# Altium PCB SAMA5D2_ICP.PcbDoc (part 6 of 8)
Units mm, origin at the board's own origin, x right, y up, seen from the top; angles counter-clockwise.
Board outline 150 x 100 mm, 6 copper layers (L1 - TOP, L2 - GND, L3 - SIG, L4 - SIG, L5 - VCC, L6 - BOT), stack 1.512 mm thick; 708 components, 597 nets, 2710 pads, 1437 vias.
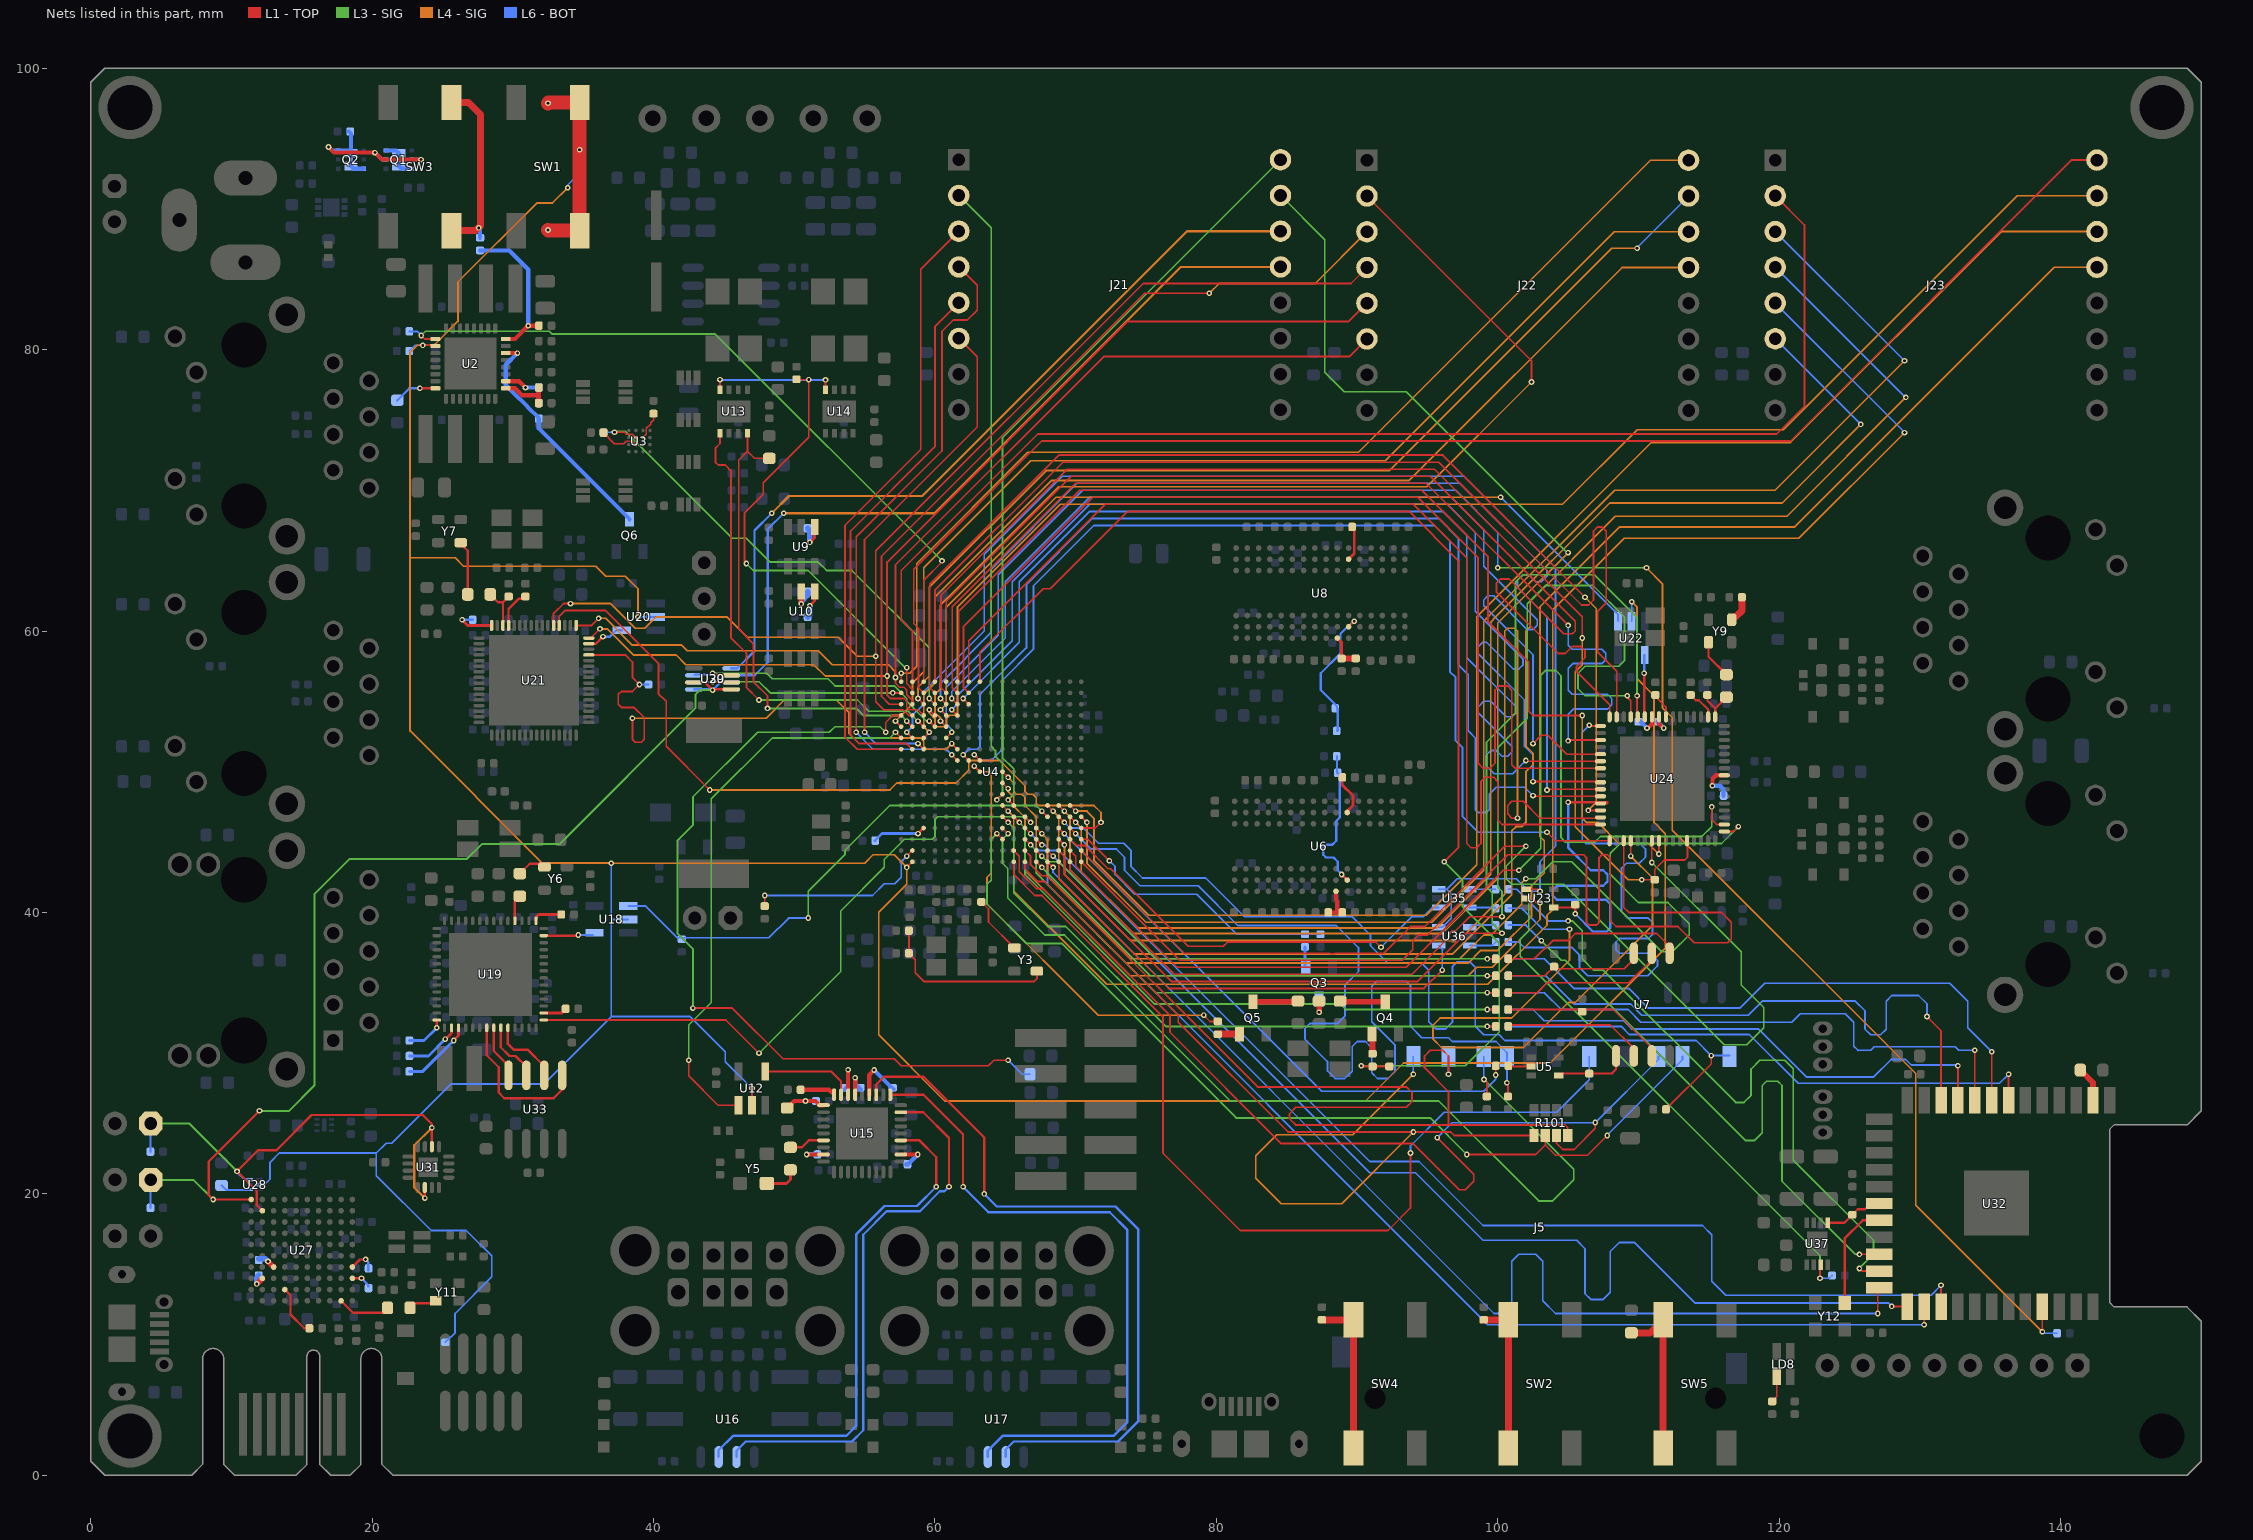
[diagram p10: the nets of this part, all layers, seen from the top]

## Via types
v1: diameter 0.4, hole 0.2, L1 - TOP to L6 - BOT, tented both sides, 1312 vias
v2: diameter 0.55, hole 0.3, L1 - TOP to L6 - BOT, 84 vias
v3: diameter 0.4, hole 0.2, L1 - TOP to L6 - BOT, tented top, 25 vias
v4: diameter 0.55, hole 0.3, L1 - TOP to L6 - BOT, tented bottom, 16 vias

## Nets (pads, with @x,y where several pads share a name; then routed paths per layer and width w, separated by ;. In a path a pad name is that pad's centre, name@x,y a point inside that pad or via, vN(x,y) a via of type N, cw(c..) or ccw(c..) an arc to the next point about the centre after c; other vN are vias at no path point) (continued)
NetLD8_4: LD8.4 R258.1 | length 1.9
  L1 - TOP w0.14: R258.1@119.5,5.25 119.825,5.575 LD8.4@119.825,7
NetQ1_2: Q1.2 Q1.5 Q2.3 Q2.6 Q2.7 Q2.8 R13.1 | length 14.1
  L1 - TOP w0.3: v1(16.9,94.4) 17.3,94 v1(20.2,94) 20.7,93.5 v1(23.475,93.5)
  L6 - BOT w0.3: v1(16.9,94.4) 17.15,94.15 Q2.3@17.587,94.15 Q2.8@18.305,94.15 ; R13.1@18.35,95.5 18.5,95.35 Q2.8@18.5,94.15 ; Q2.8@18.525,94.15 Q2.8@18.5,94.15 ; Q2.6@19.413,92.85 18.695,92.85 Q2.7@18.5,93.045 Q2.8@18.5,93.955 ; v1(20.2,94) 20.7,93.5 Q1.2@20.987,93.5 ; Q1.5@22.813,93.5 v1(23.475,93.5) ; Q2.8@18.305,94.15 Q2.8@18.5,94.15 ; Q2.8@18.305,94.15 Q2.8@18.5,93.955 ; Q2.8@18.5,93.955 Q2.8@18.5,94.15
NetQ1_3: Q1.3 Q1.6 Q1.7 Q1.8 | length 2.9
  L6 - BOT w0.3: Q1.3@20.987,94.15 21.705,94.15 Q1.8@21.9,93.955 Q1.7@21.9,93.045 22.095,92.85 Q1.6@22.813,92.85
NetQ3_1: Q3.1 R239.2 | length 1.4
  L6 - BOT w0.2: R239.2@86.3,37.55 86.3,36.2 Q3.1@86.35,36.15
NetQ3_3: Q3.3 R244.1 | length 1.7
  L1 - TOP w0.4: v1(87.3,32.9) R244.1@87.3,33.7
  L6 - BOT w0.2: v1(87.3,32.9) Q3.3@87.3,33.85
NetQ4_1: Q4.1 R240.2 | length 1.4
  L1 - TOP w0.4: Q4.1@91.05,31.35 91.1,31.3 R240.2@91.1,29.95
NetQ4_3: Q4.3 R245.1 | length 3.2
  L1 - TOP w0.4: R245.1@88.8,33.7 88.85,33.65 Q4.3@92,33.65
NetQ5_1: Q5.1 R241.2 | length 1.5
  L1 - TOP w0.5: R241.2@80.1,31.35 Q5.1@81.65,31.35
NetQ5_3: Q5.3 R246.1 | length 3.2
  L1 - TOP w0.4: Q5.3@82.6,33.65 85.75,33.65 R246.1@85.8,33.7
NetQ6_3: Q6.3 R72.1 U2.22 | length 16.6
  L1 - TOP w0.3: U2.22@29.5,79.75 v1(30.325,79.75)
  L6 - BOT w0.3: v1(30.325,79.75) 29.5,78.925 29.5,77.475 30.525,76.45 30.552,76.45 31.05,75.952 31.05,75.925 31.85,75.125 R72.1@31.85,75.1 31.85,74.4 Q6.3@38.3,67.95
NetR4_2: R4.2 R178.2 U6.L2 | length 10.5
  L1 - TOP w0.165: v1(88.9,42.7) U6.L2@89.3,42.3
  L6 - BOT w0.165: R178.2@88.575,51.1 88.575,49.95 88.775,49.75 88.775,46.75 88.525,46.5 88.525,45.1 88.225,44.8 87.8,44.8 87.6,44.6 87.6,44.1 87.8,43.9 88.325,43.9 88.625,43.6 88.625,43 v1@88.825,42.8
NetR6_2: R6.2 U2.8 | length 3.1
  L1 - TOP w0.165: v1(23.4,77.25) U2.8@24.5,77.25
  L6 - BOT w0.165: R6.2@21.8,76.4 22.65,77.25 v1(23.4,77.25)
NetR7_1: R7.1 R8.2 U2.17 | length 3.7
  L1 - TOP w0.3: U2.17@29.5,77.25 30.15,77.25 30.65,76.75 31.85,76.75 ; R7.1@31.85,76.2 31.85,76.75 ; R8.2@31.85,77.3 31.85,76.75
NetR9_1: R9.1 R10.2 U2.18 | length 3.6
  L1 - TOP w0.3: U2.18@29.5,77.75 30.45,77.75 v1(30.9,77.3)
  L6 - BOT w0.3: v1(30.9,77.3) R10.2@31.85,77.3 R9.1@31.85,76.2
NetR22_2: R22.2 U3.C2 | length 2.1
  L1 - TOP w0.1: U3.C2@39.25,73.75 39.5,74 39.5,74.4 39.8,74.7 39.8,74.8 40,75 R22.2@40,75.45 R22.2@40,75.55
NetR23_1: R23.1 U3.B3 | length 2.8
  L1 - TOP w0.1: R23.1@36.45,74.1 37.225,73.325 37.875,73.325 38.05,73.5 38.5,73.5 U3.B3@38.75,73.25
NetR27_1: R27.1 U36.1 | length 1.9
  L6 - BOT w0.125: U36.1@98,38.95 98.15,39.1 R27.1@99.85,39.1
NetR28_1: R28.1 U36.3 | length 2
  L6 - BOT w0.125: U36.3@98,37.65 99.6,37.65 R28.1@99.85,37.9
NetR29_1: R29.1 U35.1 | length 1.9
  L6 - BOT w0.125: U35.1@97.996,41.65 R29.1@99.85,41.65
NetR30_1: R30.1 U35.3 | length 1.9
  L6 - BOT w0.125: U35.3@97.996,40.35 99.8,40.35 R30.1@99.85,40.3
NetR66_1: R66.1 U4.P3 | length 3.8
  L1 - TOP w0.2: v1(58.8,45.6) U4.P3@59.2,46
  L6 - BOT w0.2: R66.1@55.75,45.1 56.25,45.6 v1(58.8,45.6)
NetR69_1: R69.1 Y3.3 | length 4.2
  L1 - TOP w0.125: R69.1@63.3,40.75 63.805,40.245 63.805,39.319 Y3.3@65.646,37.477
NetR75_2: R75.2 U4.T2 | length 13.2
  L1 - TOP w0.125: R75.2@47.9,40.45 v1(47.9,41.2) ; v1(58,44) U4.T2@58.4,44.4
  L6 - BOT w0.125: v1(47.9,41.2) 55.566,41.2 56.4,42.034 57.134,42.034 57.6,42.5 57.6,43.6 v1(58,44)
NetR83_1: R83.1 U5.4 U7.1 | length 5.2
  L1 - TOP w0.165: U5.4@104.335,28.4 104.485,28.55 108.1,28.55 ; 108.125,28.55 108.1,28.55 ; U7.1@108.4,29.775 108.4,28.85 108.1,28.55
NetR85_2: R85.2 U6.L8 | length 2.9
  L1 - TOP w0.2: R85.2@88.95,49.6 88.95,49.05 89.7,48.3 89.7,47.6 U6.L8@89.3,47.2
NetR86_2: R86.2 R87.2 U6.K1 | length 2.6
  L1 - TOP w0.305: R87.2@87.95,40 88.45,40 ; U6.K1@88.5,41.5 88.5,40.9 88.6,40.8 88.6,40.15 88.45,40 ; R86.2@88.95,40 88.45,40
NetR89_2: R89.2 R184.2 U8.L2 | length 9.8
  L1 - TOP w0.165: U8.L2@89.375,60.3 v1@89.775,60.7
  L6 - BOT w0.165: R89.2@88.575,52.9 88.625,52.95 88.625,54.45 88.575,54.5 88.575,54.66 87.425,55.81 87.425,57 88.825,58.4 88.825,59.8 v1@89.725,60.7
  other v1: 89.8,60.7
NetR91_2: R91.2 U9.4 | length 2.2
  L1 - TOP w0.2: v1(51.1,66.3) 51.125,66.3 51.45,66.625 U9.4@51.45,67.3
  L6 - BOT w0.4: R91.2@50.95,67.3 51.1,67.15 v1(51.1,66.3)
NetR92_2: R92.2 U8.L8 | length 2.5
  L1 - TOP w0.2: U8.L8@89.4,65.1 89.8,65.5 R92.2@89.8,67.4
NetR94_2: R94.2 R95.2 U8.K1 | length 2.6
  L1 - TOP w0.2: U8.K1@88.6,59.5 88.9,59.2 R95.2@88.9,58.05
  L1 - TOP w0.4: R95.2@88.9,58.05 R94.2@89.9,58.05
NetR97_1: R97.1 U10.4 | length 2
  L1 - TOP w0.2: v1(51.1,61.8) 51.125,61.8 51.45,62.125 U10.4@51.45,62.8
  L6 - BOT w0.4: R97.1@50.95,61 51.1,61.15 v1(51.1,61.8)
NetR98_1: R98.1 U10.5 | length 1.9
  L1 - TOP w0.4: v1(50.5,61.925) U10.5@50.5,62.8
  L6 - BOT w0.4: v1(50.5,61.925) 50.5,62.1 50.95,62.55 R98.1@50.95,62.8
NetR108_1: R108.1 Y5.3 | length 2.5
  L1 - TOP w0.2: Y5.3@48.055,20.742 49.444,20.742 49.733,21.031 R108.1@49.733,21.704
NetR108_2: R108.2 U15.33 | length 2.6
  L1 - TOP w0.165: R108.2@49.733,23.304 50.533,23.304 51.029,23.8 U15.33@52.08,23.8
NetR111_2: R111.2 U15.11 | length 2.4
  L1 - TOP w0.3: U15.11@57.58,22.8 v1(58.78,22.8)
  L6 - BOT w0.3: R111.2@57.95,22.1 R111.2@58.05,22.1 58.08,22.1 v1(58.78,22.8) v1@58.755,22.825
NetR112_1: R112.1 U15.35 | length 2.1
  L1 - TOP w0.3: v1(50.88,22.8) U15.35@52.08,22.8
  L6 - BOT w0.3: v1(50.88,22.8) 50.905,22.825 R112.1@51.73,22.825
NetR113_1: R113.1 U15.27 | length 2.5
  L1 - TOP w0.3: R113.1@50.45,27.4 52.48,27.4 U15.27@52.83,27.05
NetR120_1: R120.1 U15.22 | length 3.9
  L1 - TOP w0.3: U15.22@55.33,27.05 55.33,28.45 v1(55.68,28.8)
  L6 - BOT w0.3: v1(55.68,28.8) 57.03,27.45 R120.1@57.03,27.4
NetR121_1: R121.1 U15.24 | length 2.2
  L1 - TOP w0.3: U15.24@54.33,27.05 v1(54.33,28.25)
  L6 - BOT w0.3: v1(54.33,28.25) 54.33,27.8 R121.1@54.73,27.4
NetR122_1: R122.1 U15.25 | length 3.3
  L1 - TOP w0.3: U15.25@53.83,27.05 v1(53.83,28.825)
  L6 - BOT w0.3: R122.1@53.58,27.4 53.83,27.65 v1(53.83,28.825)
NetR123_1: R123.1 R124.1 U15.28 | length 3.5
  L1 - TOP w0.3: R124.1@49.5,26.1 50,26.6 v1(50.8,26.6) 51.5,26.6 51.8,26.3 U15.28@52.08,26.3
  L6 - BOT w0.3: v1(50.8,26.6) R123.1@51.378,26.6
NetR132_1: R132.1 U19.30 | length 1.7
  L1 - TOP w0.229: U19.30@32.2,32.85 33.445,32.85 R132.1@33.75,33.155
NetR133_1: R133.1 U19.43 | length 2.1
  L1 - TOP w0.229: U19.43@31.65,39.4 31.65,39.65 31.855,39.855 R133.1@33.45,39.855
NetR134_1: R134.1 U19.14 | length 2.9
  L1 - TOP w0.2: v1(24.6,31.8) U19.14@24.6,32.35
  L6 - BOT w0.2: R134.1@22.653,30.9 23.7,30.9 v1(24.6,31.8)
NetR135_1: R135.1 Y6.3 | length 1.9
  L1 - TOP w0.165: R135.1@30.5,42.755 31.2,43.455 Y6.3@32.1,43.455
NetR135_2: R135.2 U19.46 | length 1.9
  L1 - TOP w0.165: U19.46@30.15,39.4 30.15,40.805 R135.2@30.5,41.155
NetR146_2: R146.2 U21.61 | length 2.7
  L1 - TOP w0.165: U21.61@29.7,60.4 29.7,61.556 30.444,62.3 30.75,62.3 R146.2@30.9,62.45
NetR147_2: R147.2 R148.2 U21.62 | length 3.3
  L1 - TOP w0.165: R148.2@28.4,62.6 28.95,62.05 29.3,62.05 ; U21.62@29.3,60.4 29.3,62.05 ; R147.2@29.7,62.45 29.3,62.05
NetR148_1: R148.1 Y7.3 | length 3.6
  L1 - TOP w0.165: Y7.3@26.45,66.05 26.8,65.7 R148.1@26.8,62.6
NetR149_2: R149.2 U21.64 | length 3
  L1 - TOP w0.2: v1(26.4,60.8) 26.8,60.4 U21.64@28.5,60.4
  L6 - BOT w0.2: v1(26.4,60.8) R149.2@27.15,60.8
NetR150_1: R150.1 U19.16 | length 4.1
  L1 - TOP w0.2: v1(25.2,31) 25.228,31 25.5,31.272 ; 25.504,31.272 25.5,31.272 ; U19.16@25.65,31.8 25.65,31.422 25.5,31.272
  L6 - BOT w0.2: R150.1@22.653,29.8 24,29.8 v1(25.2,31)
NetR151_1: R151.1 U19.17 | length 5.1
  L1 - TOP w0.2: v1(25.8,30.9) 26.15,31.25 U19.17@26.15,31.8
  L6 - BOT w0.229: R151.1@22.65,28.7 23.6,28.7 v1(25.8,30.9)
NetR165_1: R165.1 Y9.1 | length 1.6
  L1 - TOP w0.5: Y9.1@116.85,60.95 117.371,61.471 ; 117.35,61.492 R165.1@117.35,62.4
NetR166_2: R166.2 R185.2 Y3.1 | length 12.7
  L1 - TOP w0.125: R185.2@58.15,38.7 R166.2@58.15,37.1 58.6,36.65 58.6,35.7 59.2,35.1 67.053,35.1 67.246,35.293 Y3.1@67.246,35.827
NetR168_1: R168.1 Y9.3 | length 2.8
  L1 - TOP w0.165: Y9.3@114.975,59.2 114.975,58.175 R168.1@116.25,56.9
NetR168_2: R168.2 R169.2 U24.1 | length 2.9
  L1 - TOP w0.165: R169.2@114.9,55.45 114.9,55.05 115.45,54.5 ; U24.1@115.45,53.9 115.45,54.5 ; R168.2@116.25,55.3 115.45,54.5
NetR170_2: R170.2 U24.2 | length 2.2
  L1 - TOP w0.165: R170.2@113.7,55.45 114.075,55.075 114.287,55.075 114.95,54.412 U24.2@114.95,53.9
NetR174_1: R174.1 U24.57 | length 2.8
  L1 - TOP w0.3: v1(115.25,49) 115.25,49.5 115.5,49.75 U24.57@116.1,49.75
  L6 - BOT w0.3: v1(115.25,49) 115.8,49 116.05,48.75 R174.1@116.05,48.3
NetR175_2: R175.2 U24.8 | length 1.8
  L1 - TOP w0.125: R175.2@111.2,55.35 111.95,54.6 U24.8@111.95,53.9
NetR180_1: R180.1 U24.9 | length 1.6
  L1 - TOP w0.3: U24.9@111.45,53.9 111.45,53.388 111.738,53.1 v1(111.8,53.1)
  L6 - BOT w0.3: R180.1@111.35,53.55 v1(111.8,53.1)
NetR181_1: R181.1 U24.10 | length 1.6
  L1 - TOP w0.3: v1(110.6,53.1) 110.662,53.1 110.95,53.388 U24.10@110.95,53.9
  L6 - BOT w0.3: R181.1@110.15,53.55 v1(110.6,53.1)
NetR200_2: R200.2 U27.B7 | length 3.7
  L1 - TOP w0.165: U27.B7@13.8,13.2 14.2,12.8 14.2,11.425 15.175,10.45 R200.2@15.55,10.45
NetR202_1: R202.1 Y11.3 | length 2
  L1 - TOP w0.165: R202.1@22.7,11.9 23.025,12.225 Y11.3@24.525,12.225
NetR202_2: R202.2 U27.A2 | length 3.7
  L1 - TOP w0.165: U27.A2@17.8,12.4 18.65,11.55 R202.2@21.1,11.55
NetR203_2: R203.2 U27.D1 | length 2
  L1 - TOP w0.165: U27.D1@18.6,14.8 19.14,15.34 v1(19.54,15.34)
  L6 - BOT w0.165: v1(19.54,15.34) 19.725,15.155 R203.2@19.725,14.575
NetR204_2: R204.2 U27.C1 | length 1.4
  L1 - TOP w0.165: U27.C1@18.6,14 v1(19.25,14)
  L6 - BOT w0.165: v1(19.25,14) 19.725,13.525 R204.2@19.725,13.425
NetR205_2: R205.2 U27.C9 | length 1.2
  L1 - TOP w0.4: v1(11.8,13.6) U27.C9@12.2,14
  L6 - BOT w0.4: v1(11.8,13.6) 11.8,14.05 R205.2@11.95,14.2
NetR207_2: R207.2 U27.D8 | length 1.3
  L1 - TOP w0.4: v1(12.6,15.2) U27.D8@13,14.8
  L6 - BOT w0.4: R207.2@11.95,15.4 12.4,15.4 v1(12.6,15.2)
NetR216_2: R216.2 U28.4 | length 2.1
  L6 - BOT w0.15: R216.2@9.3,20.6 9.625,20.275 11.275,20.275 U28.4@11.3,20.3
NetR247_1: R247.1 U32.19 U37.5 | length 4.4
  L1 - TOP w0.165: U37.5@123.45,17.95 124.635,17.95 R247.1@125.2,18.515 125.585,18.9 126.1,18.9 126.515,19.315 U32.19@127.12,19.315 U32.19@127.035,19.4
NetR248_1: R248.1 U32.2 | length 2.6
  L1 - TOP w0.4: R248.1@141.4,28.8 142.3,27.9 U32.2@142.3,26.655 U32.2@142.3,26.6
NetR250_2: R250.2 SW1.1 SW1.2 | length 14.7
  L1 - TOP w0.3: SW1.2@34.75,88.45 SW1.2@34.95,88.65
  L1 - TOP w1: v1(32.5,88.5) 32.55,88.45 SW1.2@34.75,88.45 v1(34.75,94.2) SW1.1@34.75,97.55 32.55,97.55 v1(32.5,97.5)
  L6 - BOT w0.5: R250.2@34.75,93.45 v1(34.75,94.2)
NetR251_2: R251.2 SW2.1 SW2.2 | length 10.9
  L1 - TOP w0.5: R251.2@99,11.05 100.625,11.05 SW2.2@100.75,11.175 ; SW2.1@100.75,1.95 SW2.2@100.75,11.05
NetR252_2: R252.2 SW3.1 SW3.2 | length 13.2
  L1 - TOP w0.5: SW3.2@25.65,88.45 27.35,88.45 27.7,88.8 27.7,96.7 26.85,97.55 SW3.1@25.65,97.55
  L6 - BOT w0.3: v1(27.575,88.65) 27.675,88.55 R252.2@27.675,87.95
NetR254_2: R254.2 SW4.1 SW4.2 | length 11.5
  L1 - TOP w0.5: R254.2@87.5,11.05 SW4.2@89.675,11.05 ; SW4.2@89.65,11.175 89.725,11.1 SW4.2@89.675,11.05 ; SW4.1@89.75,1.95 SW4.2@89.75,11.05 SW4.2@89.675,11.05
NetR255_1: R255.1 SW5.1 SW5.2 | length 12.1
  L1 - TOP w0.5: R255.1@109.5,10.125 110.825,10.125 SW5.2@111.75,11.05 SW5.1@111.75,1.95 ; SW5.2@111.75,11.55 111.75,11.275 SW5.2@111.825,11.35
NetU12_4: U12.4 U15.26 | length 6.6
  L1 - TOP w0.165: U12.4@47.945,28.7 52.63,28.7 53.33,28 U15.26@53.33,27.05
NetU18_4: U18.4 U19.41 | length 3.5
  L1 - TOP w0.165: U19.41@32.2,38.35 34.6,38.35 v1(34.65,38.4)
  L6 - BOT w0.165: v1(34.65,38.4) U18.4@35.7,38.4
NetU19_21: U19.21 U33.1 | length 10.7
  L1 - TOP w0.165: U19.21@28.15,31.8 28.15,29.85 29,29 29,27.2 29.4,26.8 32.9,26.8 33.505,27.405 U33.1@33.505,28.225
NetU19_22: U19.22 U33.4 | length 4
  L1 - TOP w0.165: U19.22@28.65,31.8 28.65,30.15 29.695,29.105 U33.4@29.695,28.425 U33.4@29.695,28.225
NetU19_23: U19.23 U33.3 | length 4.6
  L1 - TOP w0.165: U19.23@29.15,31.8 29.15,30.424 29.774,29.8 30.2,29.8 30.965,29.035 U33.3@30.965,28.425 U33.3@30.965,28.225
NetU19_24: U19.24 U33.2 | length 4.6
  L1 - TOP w0.165: U19.24@29.65,31.8 29.65,30.649 30.049,30.25 31.05,30.25 32.235,29.065 U33.2@32.235,28.825
NetU20_4: U20.4 U21.47 | length 2.7
  L1 - TOP w0.165: U21.47@35.4,59.1 35.91,59.1 v1(36.41,59.6)
  L6 - BOT w0.165: v1(36.41,59.6) 36.9,59.6 37.35,60.05 U20.4@37.75,60.05
NetU22_4: U22.4 U24.11 | length 4.4
  L1 - TOP w0.165: v1(110.4,57) 110.4,53.95 U24.11@110.45,53.9
  L6 - BOT w0.165: v1(110.4,57) 110.4,58.25 U22.4@110.45,58.3
NetU32_20: U32.20 Y12.1 | length 7.6
  L1 - TOP w0.165: Y12.1@124.65,12.25 124.65,16.825 125.94,18.115 U32.20@127.12,18.115
NRST: R2.1 R210.2 R250.1 U2.2 U4.U2 U12.2 U18.2 U20.2 U22.2 U28.2 | length 287
  L1 - TOP w0.125: v1(23.6,80.3) 24.45,80.3 U2.2@24.5,80.25 ; U12.2@47,26.3 v1(47,27.5) ; v1(58,43.2) U4.U2@58.4,43.6
  L4 - SIG w0.125: v1(33.9,91.5) 32.825,90.425 31.725,90.425 26.1,84.8 26.1,82 24.4,80.3 v1(23.6,80.3) 23.2,80.3 22.7,79.8 22.7,65.2 ; v1(38.9,61) 38.9,63 38,63.9 36.6,63.9 35.9,64.6 26.5,64.6 25.9,65.2 22.7,65.2 ; v1(109.525,62.075) 109.9,61.7 109.9,56.6 111.1,55.4 111.1,46.4 111.9,45.6 111.9,37.459 103.741,29.3 93.3,29.3 90.6,26.6 60.7,26.6 56,31.3 56,40 58,42 v1(58,43.2) 57.1,44.1 55.6,44.1 55,43.5 v1(37,43.5) 36.995,43.505 32.095,43.505 22.7,52.9 22.7,65.2
  L6 - BOT w0.125: U28.2@12,20.65 12.34,20.65 12.75,21.06 12.75,22.25 13.4,22.9 20.3,22.9 ; R2.1@22.65,79.9 23.05,80.3 v1(23.6,80.3) ; R210.2@25.21,9.45 25.9,10.14 25.9,11.5 28.5,14.1 28.5,15.6 26.7,17.4 24.2,17.4 20.3,21.3 20.3,22.9 ; v1(33.9,91.5) 33.9,91.7 R250.1@34.75,92.55 ; v1(37,43.5) 37,39.5 ; U18.2@38.2,39.5 37,39.5 ; v1(38.9,61) U20.2@40.15,61 ; v1(47,27.5) 45.1,29.4 45.1,30.1 42.6,32.6 37,32.6 ; U22.2@109.5,60.7 109.525,60.725 v1(109.525,62.075) ; 20.3,22.9 21,23.6 21.4,23.6 25.6,27.8 32.2,27.8 37,32.6 ; 37,32.6 37,39.5
NSTART: C2.2 R252.1 U2.24 | length 10.7
  L1 - TOP w0.3: U2.24@29.5,80.75 30.15,80.75 v1(31.1,81.7) C2.2@31.85,81.7
  L6 - BOT w0.3: R252.1@27.675,87.05 29.75,87.05 31.1,85.7 v1(31.1,81.7)
OCS#1: U15.13 U16.3 | length 36.8
  L1 - TOP w0.165: U15.13@57.58,23.8 58.908,23.8 60.1,22.608 v1(60.1,20.5)
  L6 - BOT w0.165: U16.3@44.625,1.31 44.625,1.775 45.65,2.8 53.7,2.8 54.4,3.5 54.4,17.118 56.417,19.135 58.735,19.135 v1(60.1,20.5)
OCS#2: U15.17 U16.2 | length 39.1
  L1 - TOP w0.165: U15.17@57.58,25.8 59.163,25.8 61,23.963 v1(61,20.5)
  L6 - BOT w0.165: U16.2@45.895,1.31 45.895,1.745 46.55,2.4 54.1,2.4 54.9,3.2 54.9,17.102 56.568,18.77 58.929,18.77 60.342,20.183 60.683,20.183 v1(61,20.5)
OCS#3: U15.19 U17.3 | length 47.9
  L1 - TOP w0.165: U15.19@56.83,27.05 59.183,27.05 62,24.233 v1(62,20.5)
  L6 - BOT w0.165: v1(62,20.5) 63.8,18.7 72.426,18.7 73.66,17.466 73.66,3.76 72.7,2.8 64.8,2.8 63.765,1.765 U17.3@63.765,1.3
OCS#4: U15.21 U17.2 | length 50.8
  L1 - TOP w0.165: U15.21@55.83,27.05 55.83,27.763 56.388,28.321 59.182,28.321 63.5,24.003 v1(63.5,20)
  L6 - BOT w0.165: v1(63.5,20) 64.4,19.1 72.825,19.1 74.458,17.467 74.458,3.858 73,2.4 65.6,2.4 65.035,1.835 U17.2@65.035,1.3
PA0: J5.5 U4.U11 | length 66.6
  L1 - TOP w0.125: U4.U11@65.6,43.6 65.6,42.7 67.1,41.2 67.6,41.2 76.2,32.6 76.2,22.9 81.7,17.4 92.2,17.4 93.8,19 v1(93.8,22.9)
  L6 - BOT w0.125: v1(93.8,22.9) 93.8,23.4 96.2,25.8 104.2,25.8 106.5,28.1 ; 106.5,28.1 J5.5@106.5,29.775
PA1: J5.2 R104.1 U4.P10 | length 67.9
  L1 - TOP w0.125: U4.P10@64.8,46 v1(65.2,45.6) ; v1(99.025,28.125) 99.225,27.925 R104.1@99.225,26.925
  L3 - SIG w0.125: v1(65.2,45.6) 64.8,45.2 64.8,43.5 65.176,43.124 65.176,41.024 67.8,38.4 69.2,38.4 81,26.6 95.8,26.6 102.9,19.5 103.9,19.5 105.4,21 105.4,21.75 v1(99.025,28.125)
  L6 - BOT w0.125: J5.2@99,29.775 99,28.125 v1(99.025,28.125)
PA2: J5.7 R101.7 U4.T11 | length 71.2
  L1 - TOP w0.125: U4.T11@65.6,44.4 66,44 66,42.9 67.2,41.7 67.7,41.7 76.7,32.7 76.7,31.5 84.625,23.575 93.995,23.575 97.27,20.3 97.7,20.3 98.3,20.9 98.3,21.4 v1(95.7,24) ; R101.7@104.175,24.15 104.175,23.6 104.625,23.15 105.425,23.15 106.925,24.65 v1(106.925,25.075)
  L6 - BOT w0.125: v1(95.7,24) 96.75,25.05 v1@106.925,25.05 ; v1@106.938,25.063 111.425,29.55 J5.7@111.425,29.775
PA3: J5.8 R101.6 U4.R10 | length 67
  L1 - TOP w0.125: v1(64.4,45.6) U4.R10@64.8,45.2 ; v1(97.8,22.8) 102.7,22.8 103.375,23.475 ; R101.6@103.375,24.15 103.375,23.475 ; 103.4,23.5 103.375,23.475 ; v1(107.775,24.15) 106.375,22.75 104.1,22.75 103.375,23.475
  L3 - SIG w0.125: v1(64.4,45.6) 64,45.2 64,42.3 63.7,42 63.7,40.6 66.5,37.8 69,37.8 81.4,25.4 95.2,25.4 v1(97.8,22.8)
  L6 - BOT w0.125: v1@107.762,24.162 113.125,29.525 J5.8@113.125,29.775
PA4: J5.9 R101.5 U4.U12 | length 75.4
  L1 - TOP w0.125: U4.U12@66.4,43.6 66.4,43.1 67.3,42.2 67.8,42.2 77.3,32.7 77.3,32.2 85.1,24.4 v1(94,24.4) 96.65,24.4 96.9,24.15 R101.5@102.575,24.15
  L4 - SIG w0.125: v1(94,24.4) 88.9,19.3 84.6,19.3 82.8,21.1 82.8,22.7 84.3,24.2 89.7,24.2 v1(94,28.5)
  L6 - BOT w0.125: v1@94,28.5 J5.9@94,29.775
PA5: J5.1 R101.8 U4.T12 | length 75.8
  L1 - TOP w0.125: U4.T12@66.4,44.4 66.8,44 66.8,43.4 67.6,42.6 67.931,42.6 82.931,27.6 93.5,27.6 93.9,27.2 93.9,26.55 93.5,26.15 85.65,26.15 85.2,25.7 85.2,25.331 85.631,24.9 96.5,24.9 ; v1(96.5,28.5) 96.5,29.8 96.1,30.2 95.2,30.2 94.8,29.8 94.8,28.95 96.5,27.25 96.5,24.9 ; R101.8@104.975,24.15 104.975,24.7 104.775,24.9 96.5,24.9
  L6 - BOT w0.125: v1@96.5,28.5 J5.1@96.5,29.775
PA6: R31.1 R32.1 U4.R12 | length 39.5
  L1 - TOP w0.125: U4.R12@66.4,45.2 v1(66.8,44.8) ; v1(99.25,34.3) R31.1@99.85,34.3
  L3 - SIG w0.125: v1(66.8,44.8) 67.2,44.4 67.2,42.8 75.7,34.3 v1(99.25,34.3)
  L6 - BOT w0.125: v1(99.25,34.3) R32.1@99.85,34.3
PA6_SCK: R31.2 U7.6 | length 11.4
  L1 - TOP w0.125: R31.2@100.75,34.3 102.8,34.3 103.5,35 109.3,35 U7.6@111.1,36.8
PA6_TXD: R32.2 U32.9 | length 40.1
  L1 - TOP w0.125: U32.9@133.9,26.655 v1@133.9,30.195
  L6 - BOT w0.125: R32.2@100.75,34.3 103.3,34.3 104.5,33.1 109.266,33.1 110.166,32.2 120.9,32.2 121.505,32.805 124.7,32.805 ; 124.7,32.8 125.305,32.195 125.305,30.495 125.6,30.2 ; 125.605,30.195 125.6,30.2 ; v1(133.9,30.2) 132.75,30.2 132.5,30.45 126.75,30.45 126.5,30.2 125.6,30.2
PA7: R33.1 R34.1 U4.T13 | length 36.4
  L1 - TOP w0.125: U4.T13@67.2,44.4 v1(67.6,44) ; v1(99.25,36.7) R33.1@99.85,36.7
  L3 - SIG w0.125: v1(67.6,44) 68,43.6 68.8,43.6 75.7,36.7 v1(99.25,36.7)
  L6 - BOT w0.125: v1(99.25,36.7) R34.1@99.85,36.7
PA7_IO0: R33.2 U7.5 | length 13.1
  L1 - TOP w0.125: R33.2@100.75,36.7 102.6,36.7 103.9,38 105,38 105.5,38.5 111.3,38.5 112.21,37.59 U7.5@112.21,37.1
PA7_RXD: R34.2 U32.8 | length 43.1
  L1 - TOP w0.125: U32.8@135.1,26.655 v1(135.1,30.1)
  L6 - BOT w0.125: R34.2@100.75,36.7 103.3,36.7 105.4,34.6 109.3,34.6 110.7,33.2 117.2,33.2 118.975,34.975 132.125,34.975 133.4,33.7 133.4,31.8 v1(135.1,30.1)
PA8: R35.1 R36.1 U4.N10 | length 44.5
  L1 - TOP w0.125: U4.N10@64.8,46.8 v1(65.2,46.4) ; v1(99.25,31.9) R35.1@99.85,31.9
  L3 - SIG w0.125: v1(65.2,46.4) 65.6,46 65.6,41.4 68,39 69.3,39 76.4,31.9 v1(99.25,31.9)
  L6 - BOT w0.125: v1(99.25,31.9) R36.1@99.85,31.9
PA8_IO1: R35.2 U7.2 | length 9.7
  L1 - TOP w0.125: R35.2@100.75,31.9 100.85,32 108,32 U7.2@109.7,30.3
PA8_W3K_RST: R36.2 U32.7 | length 39.3
  L1 - TOP w0.125: U32.7@136.3,26.655 v1(136.3,28.5)
  L6 - BOT w0.125: R36.2@100.75,31.9 108.769,31.9 109.344,31.325 117.875,31.325 121.341,27.859 135.659,27.859 v1(136.3,28.5)
PA9: R37.1 R38.1 U4.N11 | length 42.5
  L1 - TOP w0.125: U4.N11@65.6,46.8 v1(66,46.4) ; v1(99.25,33.1) R37.1@99.85,33.1
  L3 - SIG w0.125: v1(66,46.4) 66.4,46 66.4,42.7 75.6,33.5 88.8,33.5 89.2,33.1 v1(99.25,33.1)
  L6 - BOT w0.125: v1(99.25,33.1) R38.1@99.85,33.1
PA9_CTS: R38.2 U32.10 | length 37.1
  L1 - TOP w0.125: U32.10@132.7,26.655 v1(132.7,29.1)
  L6 - BOT w0.125: R38.2@100.75,33.1 102.5,33.1 103.3,32.3 108.934,32.3 109.509,31.725 118.5,31.725 121.914,28.311 126.711,28.311 127.95,29.55 129,29.55 129.4,29.15 132.65,29.15 v1(132.7,29.1)
PA9_IO2: R37.2 R84.1 U7.3 | length 11.6
  L1 - TOP w0.125: R37.2@100.7,33.1 R37.2@100.75,33.1 108.2,33.1 U7.3@111.1,30.2
PA10: R39.1 R40.1 U4.U13 | length 36.6
  L1 - TOP w0.125: U4.U13@67.2,43.6 v1(67.6,43.2) ; v1(99.25,35.5) R39.1@99.85,35.5
  L3 - SIG w0.125: v1(67.6,43.2) 75.3,35.5 v1(99.25,35.5)
  L6 - BOT w0.125: v1(99.25,35.5) R40.1@99.85,35.5
PA10_IO3: R39.2 R88.1 U7.7 | length 9.4
  L1 - TOP w0.125: R39.2@100.75,35.5 103.35,35.5 R88.1@104,36.15 ; R88.1@104,36 109,36 U7.7@109.6,36.6
PA10_RTS: R40.2 U32.11 | length 42.9
  L1 - TOP w0.125: v1(130.5,32.6) 131.5,31.6 U32.11@131.5,26.655
  L6 - BOT w0.125: R40.2@100.75,35.5 103.4,35.5 105.4,33.5 109.431,33.5 110.231,32.7 117.8,32.7 118.8,33.7 125.4,33.7 126.1,33 126.1,31.7 126.5,31.3 127.2,31.3 127.6,31.7 127.6,33.7 128,34.1 129.9,34.1 130.5,33.5 v1(130.5,32.6)
PA11: R41.1 U4.P15 | length 40.1
  L1 - TOP w0.125: U4.P15@68.8,46 v1(69.2,45.6) ; v1(99.85,28.45) R41.1@99.85,29.1
  L6 - BOT w0.125: v1(69.2,45.6) 87.5,27.3 99,27.3 99.85,28.15 v1(99.85,28.45)
PA11_CS: R41.2 U5.2 | length 1.6
  L1 - TOP w0.125: R41.2@100.825,29.075 100.85,29.05 U5.2@102.375,29.05
PA12: J5.11 R102.1 U4.N15 | length 71.9
  L1 - TOP w0.125: U4.N15@68.8,46.8 v1(69.2,46.4) ; R102.1@111.95,26 115.175,29.225 v1(115.175,29.825)
  L6 - BOT w0.125: v1(69.2,46.4) 69.6,46 70.55,46 71.625,44.925 73.425,44.925 73.925,44.425 73.925,43.275 74.75,42.45 79.25,42.45 82,39.7 89.65,39.7 90.95,38.4 90.95,37.65 92.2,36.4 94.6,36.4 95.1,35.9 95.1,32.225 95.6,31.725 96.3,31.725 96.775,32.2 96.775,36.15 97.125,36.5 98,36.5 98.4,36.1 98.4,31.9 99,31.3 100.1,31.3 100.5,30.9 114.1,30.9 v1(115.175,29.825) J5.11@116.475,29.825
PA13: J5.10 R103.1 U4.P16 | length 69.5
  L1 - TOP w0.125: U4.P16@69.6,46 v1(70,45.6) ; v1(100.65,27.9) 100.725,27.825 R103.1@100.725,26.925
  L6 - BOT w0.125: v1(70,45.6) 71.1,44.5 72.9,44.5 73.475,43.925 73.475,43 74.575,41.9 78.7,41.9 81.525,39.075 88.525,39.075 90.1,37.5 90.1,35.8 89.15,34.85 89.15,32.65 88.6,32.1 86.65,32.1 86.3,31.75 86.3,31 87.9,29.4 87.9,28.737 88.437,28.2 89.125,28.2 89.65,28.725 89.65,30.47 90.005,30.825 90.6,30.825 91.05,30.375 91.05,28.6 91.45,28.2 92.2,28.2 92.7,28.7 92.7,30.575 91.05,32.225 91.05,34.75 91.4,35.1 93.5,35.1 93.8,34.8 93.8,31.9 94.6,31.1 96.5,31.1 96.775,30.825 99.875,30.825 100.65,30.05 J5.10@100.65,29.775 v1@100.65,27.95
PA14: J23.4 U4.M14 | length 109.5
  L1 - TOP w0.125: U4.M14@68,47.6 v1(68.4,47.2)
  L4 - SIG w0.125: v1(68.4,47.2) 68.8,46.8 68.8,42.4 74.15,37.05 96.788,37.05 101,41.262 101,45.8 101.3,46.1 101.7,46.1 102,46.4 102,50 102.5,50.5 102.5,51.3 102,51.8 102,60 102.308,60.308 102.308,62.1 108.358,68.15 119.6,68.15 120.55,68.15 v1(129,76.6)
  L6 - BOT w0.125: J23.4@119.72,85.845 128.965,76.6 v1(129,76.6)
PA15: J23.6 U4.N16 | length 95.5
  L1 - TOP w0.125: U4.N16@69.6,46.8 v1(70,46.4)
  L4 - SIG w0.125: v1(70,46.4) 70.4,46 70.4,42.9 74.4,38.9 95.7,38.9 99.5,42.7 99.5,60.636 99.864,61 107.964,69.1 118.8,69.1 120.215,69.1 v1(125.8,74.685) ; J23.6@119.292,81.192 J23.6@119.5,81.4
  L6 - BOT w0.125: J23.6@119.72,80.765 v1(125.8,74.685)
PA16: J23.5 U4.M10 | length 114.6
  L1 - TOP w0.125: U4.M10@64.8,47.6 v1(65.2,47.2)
  L4 - SIG w0.125: v1(65.2,47.2) 65.6,46.8 65.6,41.5 72.2,34.9 99.3,34.9 103.5,39.1 103.5,39.8 103.9,40.2 103.9,61.5 109,66.6 119.6,66.6 121.4,66.6 v1(128.9,74.1)
  L6 - BOT w0.125: J23.5@119.72,83.305 128.9,74.125 v1(128.9,74.1)
PA17: J23.3 U4.N17 | length 103.2
  L1 - TOP w0.125: U4.N17@70.4,46.8 v1(70.8,46.4)
  L4 - SIG w0.125: v1(70.8,46.4) 70.8,43.5 75,39.3 95.3,39.3 99,43 99,60.701 99.899,61.6 107.599,69.3 108.299,70 119.7,70 v1(128.9,79.2)
  L6 - BOT w0.125: J23.3@119.72,88.385 128.9,79.205 v1(128.9,79.2)
PA18: U4.U14 U32.24 | length 81.4
  L1 - TOP w0.125: U4.U14@68,43.6 v1(68.4,43.2) ; v1(127,11.5) 127,13.195 U32.24@127.12,13.315
  L6 - BOT w0.125: v1(68.4,43.2) 68.4,42.834 99.734,11.5 100.6,11.5 101,11.9 101,15.2 101.5,15.7 102.7,15.7 103.2,15.2 103.2,12.4 104.1,11.5 v1(127,11.5)
PA19: U4.T14 U32.25 | length 81.5
  L1 - TOP w0.125: U4.T14@68,44.4 v1(68.4,44) ; v1(128,12) 129.075,12 U32.25@129.1,11.975
  L6 - BOT w0.125: v1(68.4,44) 90.9,21.5 94.15,21.5 98.95,16.7 105.6,16.7 106.2,16.1 106.2,12.9 106.6,12.5 107.5,12.5 108,13 108,15.9 108.65,16.55 109.7,16.55 114,12.25 127.75,12.25 v1(128,12)
PA20: U4.P12 U32.26 | length 81.4
  L1 - TOP w0.125: U4.P12@66.4,46 v1(66.8,45.6) ; v1(130.3,10.7) U32.26@130.3,11.975
  L6 - BOT w0.125: v1(66.8,45.6) 67.2,45.2 67.2,44.6 67.4,44.4 67.775,44.4 68,44.175 68,42 99.3,10.7 v1(130.3,10.7)
PA21: U4.R13 U32.27 | length 81.5
  L1 - TOP w0.125: U4.R13@67.2,45.2 v1(67.6,44.8) ; U32.27@131.5,11.975 v1(131.5,13.5)
  L6 - BOT w0.125: v1(67.6,44.8) 67.8,44.8 68.2,44.4 68.8,44.4 90.9,22.3 94.4,22.3 98.95,17.75 114.55,17.75 115.2,17.1 115.2,13.8 116.2,12.8 130.8,12.8 v1(131.5,13.5)
PA22: U4.U15 U36.4 | length 34.1
  L1 - TOP w0.125: U4.U15@68.8,43.6 68.8,42.4 76.6,34.6 94.75,34.6 v1(96.05,35.9)
  L6 - BOT w0.125: U36.4@95.8,37.65 96.096,37.354 96.05,37.309 v1(96.05,35.9)
PA22_CK: R27.2 U32.22 | length 45.5
  L1 - TOP w0.125: v1(125.7,15.7) 125.715,15.715 U32.22@127.12,15.715
  L3 - SIG w0.125: v1(103.1,38) 104.5,36.6 104.8,36.6 117.6,23.8 118.25,23.8 118.8,24.35 118.8,27.7 119.1,28 119.9,28 120.2,27.7 120.2,20.9 125.4,15.7 v1(125.7,15.7)
  L6 - BOT w0.125: R27.2@100.75,39.1 102,39.1 v1(103.1,38)
PA22_D0: R28.2 U24.17 | length 42.4
  L1 - TOP w0.125: v1(106.5,53.3) 106.55,53.25 U24.17@107.3,53.25
  L6 - BOT w0.125: R28.2@100.75,37.9 101.5,37.9 101.9,37.5 105.3,37.5 105.8,37 105.8,36.1 106.4,35.5 110.65,35.5 111.35,36.2 111.35,36.6 110.85,37.1 108.65,37.1 108.4,37.35 108.4,37.9 108.65,38.15 110.7,38.15 111,38.45 111,39.3 110.7,39.6 109.25,39.6 108.8,40.05 108.8,43.15 109.15,43.5 110.066,43.5 110.5,43.934 110.5,44.5 110.1,44.9 106.25,44.9 106,45.15 106,52.8 v1(106.5,53.3)
PA23: U4.U16 U24.13 | length 81
  L1 - TOP w0.125: U4.U16@69.6,43.6 69.6,43 77,35.6 93.9,35.6 96.517,38.217 96.517,38.458 96.742,38.683 96.983,38.683 98,39.7 v1(100.3,39.7) ; v1(109.2,55.4) 109.2,55.3 109.45,55.05 U24.13@109.45,53.9
  L3 - SIG w0.125: v1(100.3,39.7) 100.3,41.5 100,41.8 100,51.7 102.1,53.8 102.1,61.95 103.381,63.231 106.769,63.231 109,61 109,57.9 108.6,57.5 106.2,57.5 105.7,57 105.7,55.9 106.2,55.4 v1(109.2,55.4)
PA24: U4.T15 U24.12 | length 81
  L1 - TOP w0.125: U4.T15@68.8,44.4 69.2,44 69.2,42.7 76.8,35.1 94.3,35.1 97.72,38.52 v1(100.3,38.52) ; v1(109.9,55.4) 109.9,53.95 U24.12@109.95,53.9
  L3 - SIG w0.125: v1(100.3,38.52) 99.6,39.22 99.6,41.4 99.2,41.8 99.2,52.1 101.251,54.151 101.251,63.451 101.8,64 106.849,64 109.9,60.949 v1(109.9,55.4)
PA25: U4.U17 U24.35 | length 81.5
  L1 - TOP w0.125: U4.U17@70.4,43.6 77.4,36.6 93.2,36.6 93.95,37.35 93.95,37.98 94.37,38.4 95,38.4 100.7,44.1 106.1,44.1 106.3,43.9 106.3,39.3 106.5,39.1 107,39.1 107.2,39.3 107.2,43.9 107.4,44.1 107.8,44.1 108,43.9 108,39.4 108.4,39 112.8,39 113.95,37.85 116.35,37.85 116.6,38.1 116.6,39.3 115.9,40 109.3,40 108.95,40.35 U24.35@108.95,45.1
PA25_3U: J20.1 R220.1 U27.K10 U29.1 U29.7 U30.1 U30.7 | length 76.5
  L1 - TOP w0.165: U27.K10@11.4,19.6 v1(8.7,19.6) 8.4,19.9 8.4,22.3 v1(12,25.9) ; U30.7@42.875,56.35 43.65,56.35 44.15,55.85 U30.1@45.525,55.85
  L3 - SIG w0.14: J20.1@4.27,21 7.3,21 v1(8.7,19.6) ; v1(12,25.9) 14.1,25.9 15.9,27.7 15.9,41.3 18.4,43.8 26.745,43.8 27.8,44.855 33.321,44.855 43,54.534 43,55.5 43.3,55.8 v1(44.2,55.8)
  L6 - BOT w0.165: R220.1@4.25,19 4.25,20.98 J20.1@4.27,21 ; U29.1@42.875,55.85 44.25,55.85 44.75,56.35 U29.7@45.525,56.35
PA26: U4.P13 U24.49 | length 79
  L1 - TOP w0.125: U4.P13@67.2,46 v1(67.6,45.6) ; U24.49@116.1,45.75 116.75,45.75 v1(117.1,46.1)
  L3 - SIG w0.125: v1(102,42.4) 102.7,42.4 103.9,43.6 105.25,43.6 111.65,37.2 112.4,37.2 113.6,38.4 113.6,39.2 112.1,40.7 110,40.7 108,42.7 108,44.2 108.7,44.9 115.9,44.9 v1(117.1,46.1)
  L4 - SIG w0.125: v1(67.6,45.6) 68,45.2 68,42.625 73.925,36.7 97.3,36.7 99,38.4 99.523,38.4 101.7,40.577 101.7,42.1 v1(102,42.4)
PA26_3U: J19.1 R217.1 U27.J9 U28.6 U31.2 U31.10 | length 38.6
  L1 - TOP w0.15: U31.10@24.25,23.35 U31.10@24.25,23.5
  L1 - TOP w0.165: U27.J9@12.2,18.8 11.8,19.2 11.8,20.2 v1(10.4,21.6) 11.9,23.1 13.2,23.1 15.7,25.6 23.6,25.6 23.9,25.3 ; 23.65,25.55 24.25,24.95 U31.10@24.25,23.5 ; v1(23.75,19.7) U31.2@23.75,20.45
  L3 - SIG w0.14: J19.1@4.27,25 7,25 v1(10.4,21.6)
  L4 - SIG w0.165: v1(23.75,19.7) 23,20.45 23,23.45 v1(24.25,24.7)
  L6 - BOT w0.165: R217.1@4.25,23 4.25,24.98 J19.1@4.27,25 ; v1(10.4,21.6) 10.4,21.56 10.96,21 U28.6@11.3,21
PA27: U4.T16 U24.50 | length 81
  L1 - TOP w0.125: U4.T16@69.6,44.4 70,44 70,43.3 77.2,36.1 93.5,36.1 100.4,43 v1(101.5,43) ; v1(115.2,47.5) 115.2,46.599 115.549,46.25 U24.50@116.1,46.25
  L3 - SIG w0.125: v1(101.5,43) 103.05,44.55 103.05,56.85 103.4,57.2 104.1,57.2 104.5,56.8 104.5,45.3 104.8,45 106.9,45 107.3,45.4 114.5,45.4 115.2,46.1 v1(115.2,47.5)
PA28: U4.R16 U35.4 | length 30.8
  L1 - TOP w0.125: U4.R16@69.6,45.2 70.035,44.765 70.635,44.765 72.3,43.1 72.5,43.1 78,37.6 80.5,37.6 80.8,37.9 91.325,37.9 v1(91.7,37.525)
  L6 - BOT w0.125: v1(91.7,37.525) 93.875,39.7 94.7,39.7 95.35,40.35 U35.4@95.796,40.35
PA28_CMD: R29.2 U32.23 | length 48.8
  L1 - TOP w0.125: v1(125.7,14.7) 125.885,14.515 U32.23@127.12,14.515
  L3 - SIG w0.125: v1(105,39.4) 105.3,39.4 106,38.7 106,36.7 106.8,35.9 107.5,35.9 116.9,26.5 117.5,26.5 118,27 118,28.875 118.625,29.5 120.4,29.5 121,28.9 121,22.4 126.7,16.7 126.7,15.7 v1(125.7,14.7)
  L6 - BOT w0.125: R29.2@100.75,41.65 101.35,41.65 103.6,39.4 v1(105,39.4)
PA28_D6: R30.2 U24.36 | length 45.9
  L1 - TOP w0.125: v1(109.45,44) U24.36@109.45,45.1
  L4 - SIG w0.125: v1(105.1,38.8) 105.1,36.6 101,32.5 95.9,32.5 95.4,32 95.4,31 96,30.4 101.8,30.4 105,33.6 105.5,33.6 111,39.1 111,42.45 v1(109.45,44)
  L6 - BOT w0.125: R30.2@100.75,40.3 101.7,40.3 103.2,38.8 v1(105.1,38.8)
PA29: U4.T17 U24.39 | length 81
  L1 - TOP w0.125: U4.T17@70.4,44.4 77.7,37.1 88.059,37.1 88.092,37.067 88.408,37.067 88.441,37.1 91.9,37.1 93.804,39.004 94.8,39.004 100.496,44.7 v1(102,44.7) ; v1(110.95,43.55) U24.39@110.95,45.1
  L3 - SIG w0.125: v1(102,44.7) 100.6,43.3 100.6,42.4 101,42 104.7,42 116.1,30.6 117.7,30.6 118.9,31.8 118.9,33.241 117.3,34.841 117.3,37.2 v1(110.95,43.55) v1@110.9,43.5
PA30: U4.R15 U24.30 | length 79.1
  L1 - TOP w0.125: U4.R15@68.8,45.2 v1(69.2,44.8) ; v1(101.4,46.7) 101,46.7 100.7,47 100.7,47.6 101,47.9 101.8,47.9 103,46.7 107.25,46.7 U24.30@107.3,46.75
  L4 - SIG w0.125: v1(69.2,44.8) 69.2,42.725 73.925,38 96.677,38 96.747,37.93 97.053,37.93 97.123,38 97.217,38 100.5,41.283 100.5,60 100.7,60.2 101.2,60.2 101.4,60 v1(101.4,46.7)
PA31: R239.1 R242.2 U4.R17 | length 20.1
  L1 - TOP w0.125: U4.R17@70.4,45.2 70.85,45.2 72.375,43.675 v1(72.4,43.675)
  L6 - BOT w0.125: v1(72.4,43.675) 72.8,43.275 72.8,42.7 74.2,41.3 78.6,41.3 81.45,38.45 R242.2@87.4,38.45
PB0: R241.1 U4.J8 | length 31.2
  L1 - TOP w0.125: v1(62.8,50.4) U4.J8@63.2,50 ; v1(79.1,32.7) 79.55,32.25 R241.1@80.1,32.25
  L4 - SIG w0.125: v1(62.8,50.4) 63.2,50 63.8,50 64,49.8 64,42.8 63.7,42.5 63.7,40.6 71.6,32.7 v1(79.1,32.7)
PB1: R240.1 R243.2 U4.A8 | length 90
  L1 - TOP w0.125: U4.A8@63.2,56.4 63.2,58.516 67.684,63 68.2,63 73.7,68.5 93.7,68.5 97.2,65 97.2,44.6 v1(96.2,43.6) ; v1(90.3,29.1) 90.35,29.05 R240.1@91.1,29.05 R243.2@92.3,29.05
  L3 - SIG w0.125: v1(90.3,29.1) 97.7,29.1 100.1,31.5 100.1,37.8 97.5,40.4 97.5,42.3 v1(96.2,43.6)
PB2: U4.A7 U24.31 | length 81.5
  L1 - TOP w0.125: U4.A7@62.4,56.4 62.4,59.3 72.1,69 94,69 97.8,65.2 97.8,44.9 98.1,44.6 98.5,44.6 98.8,44.9 98.8,49.3 99.1,49.6 99.7,49.6 100,49.3 100,46.55 100.3,46.25 U24.31@107.3,46.25
PB3: U4.A6 U24.40 | length 79
  L1 - TOP w0.125: U4.A6@61.6,56.4 61.694,56.494 61.694,61.394 70.3,70 94.6,70 99.3,65.3 99.3,60.7 102.2,57.8 102.2,54.3 102.5,54 v1(106,54) ; v1(111.45,44.15) U24.40@111.45,45.1
  L4 - SIG w0.125: v1(106,54) 106,46.7 106.3,46.4 107.1,46.4 108.6,44.9 110.7,44.9 v1(111.45,44.15)
PB4: U4.B6 U24.19 | length 78.5
  L1 - TOP w0.125: U4.B6@61.6,55.6 61.235,55.965 61.235,61.735 70,70.5 94.9,70.5 v1(105,60.4) ; v1(105,52.19) 105,52.2 105.05,52.25 U24.19@107.3,52.25
  L6 - BOT w0.125: v1(105,52.19) 105,54.087 105.362,54.45 107.8,54.45 108.1,54.75 108.1,55.2 107.8,55.5 105.3,55.5 105,55.8 105,57.35 105.35,57.7 107.426,57.7 107.676,57.95 107.676,58.424 107.4,58.7 105.3,58.7 105,59 v1(105,60.4)
PB5: U4.B7 U24.23 | length 81.5
  L1 - TOP w0.125: U4.B7@62.4,55.6 62.035,55.965 62.035,60.33 71.205,69.5 94.3,69.5 98.6,65.2 98.6,50.6 98.95,50.25 99.45,50.25 99.8,50.6 99.8,55.8 100.1,56.1 100.7,56.1 101,55.8 101,50.5 101.25,50.25 U24.23@107.3,50.25
PB6: U4.C7 U24.22 | length 78.6
  L1 - TOP w0.125: v1(62,55.2) U4.C7@62.4,54.8 ; v1(102,50.8) 102,50.7 102.05,50.75 U24.22@107.3,50.75
  L6 - BOT w0.125: v1(62,55.2) 66,59.2 66,63.5 71,68.5 96.1,68.5 97.8,66.8 97.8,58.1 101.3,54.6 101.3,54.2 101,53.9 100.6,53.9 99.5,55 99,55 98.6,54.6 98.6,54.2 101,51.8 101,51.4 100.7,51.1 100.3,51.1 99.9,51.5 99.5,51.5 99.2,51.2 99.2,50.4 99.75,49.85 101.05,49.85 v1(102,50.8)
PB7: U4.C6 U24.21 | length 78.5
  L1 - TOP w0.125: v1(61.2,55.2) U4.C6@61.6,54.8 ; v1(102.5,52) 103.1,52.6 103.55,52.6 104.9,51.25 106.125,51.25 U24.21@107.3,51.25
  L6 - BOT w0.125: v1(61.2,55.2) 61.2,55.7 65,59.5 65,63.49 71.01,69.5 96.7,69.5 99,67.2 99,64.6 102.8,60.8 102.8,60.4 102.5,60.1 102.1,60.1 99.7,62.5 99.3,62.5 99,62.2 99,61.8 102.5,58.3 v1(102.5,52)
PB8: U4.A5 U24.16 | length 81.5
  L1 - TOP w0.125: U4.A5@60.8,56.4 60.8,62.1 69.7,71 95.2,71 105.5,60.7 105.5,60 105.3,59.8 104.7,59.8 100.8,63.7 100.2,63.7 99.9,63.4 99.9,62.8 104.3,58.4 104.8,58.4 105.3,58.9 105.9,58.9 106.2,58.6 106.2,58.1 105.6,57.5 105.6,57.1 107.95,54.75 U24.16@107.95,53.9
PB9: U4.A4 U24.15 | length 81.5
  L1 - TOP w0.125: U4.A4@60,56.4 60,62.9 69.1,72 95.8,72 105.95,61.85 106.45,61.85 106.8,62.2 106.8,67.1 107.1,67.4 107.4,67.4 107.7,67.1 107.7,62 107.1,61.4 107.1,58.5 108.45,57.15 U24.15@108.45,53.9
PB10: U4.H8 U24.33 | length 78.5
  L1 - TOP w0.125: v1(62.8,51.2) U4.H8@63.2,50.8 ; v1(103.5,45.7) 104.1,45.1 U24.33@107.95,45.1
  L6 - BOT w0.125: v1(62.8,51.2) 63.2,50.8 64,50.8 64.8,51.6 64.8,56.5 67,58.7 67,63.2 71.3,67.5 95.5,67.5 96.6,66.4 96.6,57.1 97,56.7 97,52.2 97.5,51.7 97.5,46.8 98.6,45.7 v1(103.5,45.7)
PB11: R171.1 U4.B5 U24.44 | length 87.6
  L1 - TOP w0.125: U4.B5@60.8,55.6 60.435,55.965 60.435,62.535 69.4,71.5 95.5,71.5 106,61 v1(106,59.5) ; v1(110.225,42.325) R171.1@111.15,42.325 111.15,43.05 111.825,43.725 113.281,43.725 113.483,43.927 113.483,45.067 U24.44@113.45,45.1
  L4 - SIG w0.125: v1(106,59.5) 106,57.6 105.5,57.1 105.5,46.1 109.275,42.325 v1(110.225,42.325)
PB12: U4.D6 U24.25 | length 78.6
  L1 - TOP w0.125: v1(61.2,54.4) U4.D6@61.6,54 ; v1(102.5,49.3) 107.25,49.3 U24.25@107.3,49.25
  L6 - BOT w0.125: v1(61.2,54.4) 61.6,54.8 61.6,55.4 65.5,59.3 65.5,63.495 71.005,69 96.4,69 98.4,67 98.4,61.4 101.8,58 101.8,57.6 101.5,57.3 101.1,57.3 99.2,59.2 98.92,59.2 98.5,58.78 98.5,58.5 101.9,55.1 101.9,51.8 102.5,51.2 v1(102.5,49.3)
PB13: U4.B4 U24.29 | length 79
  L1 - TOP w0.125: U4.B4@60,55.6 59.635,55.965 59.635,63.335 68.8,72.5 96.1,72.5 v1(106.2,62.4) ; v1(106.425,47.25) U24.29@107.3,47.25
  L4 - SIG w0.125: v1(106.2,62.4) 107,61.6 107,47.825 v1(106.425,47.25)
PB14: U4.C5 U24.26 | length 78.5
  L1 - TOP w0.125: v1(60.4,55.2) U4.C5@60.8,54.8 ; v1(103.5,48.7) 103.55,48.75 U24.26@107.3,48.75
  L6 - BOT w0.125: v1(60.4,55.2) 60.4,56.3 64,59.9 64,64.4 70.1,70.5 97.3,70.5 103.5,64.3 103.5,63.9 103.1,63.5 102.7,63.5 102.2,64 101.756,64 101.4,63.644 101.4,63.1 103.5,61 v1(103.5,48.7)
PB15: U4.H7 U24.27 | length 78.5
  L1 - TOP w0.125: v1(62,51.2) U4.H7@62.4,50.8 ; v1(102.5,48.3) 102.55,48.25 U24.27@107.3,48.25
  L6 - BOT w0.125: v1(62,51.2) 62.4,51.6 63,51.6 63.2,51.8 63.2,55.5 66.5,58.8 66.5,63.3 71.2,68 95.8,68 97.2,66.6 97.2,57.6 97.9,56.9 97.9,52.9 98.4,52.4 98.4,47.3 98.6,47.1 99.2,47.1 99.4,47.3 99.4,48.4 99.9,48.9 101.9,48.9 v1(102.5,48.3)
PB16: U4.D5 U22.1 | length 62.9
  L1 - TOP w0.125: v1(60.4,54.4) U4.D5@60.8,54
  L4 - SIG w0.125: v1(60.4,54.4) 60.8,54.8 60.8,61.695 68.605,69.5 v1(100.2,69.5)
  L6 - BOT w0.125: v1(100.2,69.5) 108.55,61.15 U22.1@108.55,60.7
PB17: R24.1 U3.C3 U4.C4 | length 35.4
  L1 - TOP w0.1: v1(37.225,74.125) 37.95,74.125 38.075,74 38.5,74 U3.C3@38.75,73.75
  L1 - TOP w0.125: v1(59.6,55.2) U4.C4@60,54.8
  L3 - SIG w0.125: v1(37.225,74.125) 37.3,74.2 38,74.2 45.6,66.6 46.6,66.6 48.3,64.9 51.7,64.9 52.3,64.3 54.1,64.3 59.6,58.8 v1(59.6,55.2)
  L6 - BOT w0.125: R24.1@36.45,74.1 36.475,74.125 v1(37.225,74.125)
PB18: R1.1 U2.1 U4.A3 | length 55.1
  L1 - TOP w0.125: v1(23.5,81) 23.75,80.75 U2.1@24.5,80.75 ; U4.A3@59.2,56.4 59.2,63.6 v1@60.54,64.94
  L3 - SIG w0.125: v1(23.5,81) 23.8,81.3 32.6,81.3 32.8,81.1 44.38,81.1 v1(60.5,64.98)
  L6 - BOT w0.14: R1.1@22.65,81.3 23.2,81.3 v1(23.5,81)
PB19: J23.15 U4.D4 | length 104.7
  L1 - TOP w0.125: v1(59.6,54.4) U4.D4@60,54
  L4 - SIG w0.125: v1(59.6,54.4) 59.6,54.175 60,53.775 60,53.3 60.1,53.2 60.631,53.2 60.815,53.385 60.815,53.775 61.045,54.005 61.405,54.005 61.6,54.2 61.6,61.7 68.9,69 104.6,69 109.9,74.3 120.3,74.3 136.925,90.925 J23.15@142.58,90.925
PB20: J23.16 U4.B3 | length 105.2
  L1 - TOP w0.125: U4.B3@59.2,55.6 58.835,55.965 58.835,60.2 58.5,60.535 58.5,64.4 67.6,73.5 120.8,73.5 140.765,93.465 J23.16@142.58,93.465
PB21: J23.2 U4.A2 | length 93.1
  L1 - TOP w0.125: U4.A2@58.4,56.4 58.4,60 57.6,60.8 57.6,64.3 67.3,74 119.825,74 121.8,75.975 121.8,88.845 J23.2@119.72,90.925
PB22: J22.15 U4.C3 | length 74.3
  L1 - TOP w0.125: v1(58.8,55.2) U4.C3@59.2,54.8
  L4 - SIG w0.125: v1(58.8,55.2) 58.8,56 59.6,56.8 59.6,63.1 67.9,71.4 92.3,71.4 108.1,87.2 v1(109.9,87.2)
  L6 - BOT w0.125: v1(109.9,87.2) 109.9,87.255 J22.15@113.56,90.915
PB23: J22.16 U4.A1 | length 75.9
  L1 - TOP w0.125: U4.A1@57.6,56.4 v1(57.6,57)
  L4 - SIG w0.125: v1(57.6,57) 58.2,57 58.7,57.5 58.7,64.8 66.6,72.7 90.1,72.7 110.855,93.455 J22.16@113.56,93.455
PB24: J22.2 U4.E5 | length 75.8
  L1 - TOP w0.125: v1(60.4,53.6) U4.E5@60.8,53.2 ; J22.2@90.7,90.915 102.4,79.215 v1(102.4,77.7)
  L4 - SIG w0.125: v1(60.4,53.6) 60.4,53.8 60,54.2 60,55.5 60.4,55.9 60.4,61.861 68.789,70.25 94.95,70.25 v1(102.4,77.7)
PB25: R107.1 U4.B2 U13.8 U14.8 | length 41
  L1 - TOP w0.125: U13.8@44.675,77.2 U13.8@44.725,77.15 v1(44.725,77.863) ; v1(46.6,64.8) 46.475,64.925 46.475,68.4 47.8,69.725 47.8,70.55 51.031,73.781 v1(51.031,77.863) R107.1@50.387,77.863 ; U14.8@52.219,77.131 v1(52.219,77.844) ; v1(58,57.4) 58,56.268 58.4,55.868 U4.B2@58.4,55.6
  L3 - SIG w0.125: v1(46.6,64.8) 47.1,64.3 51,64.3 57.9,57.4 v1(58,57.4)
  L6 - BOT w0.125: v1@44.744,77.844 v1(52.219,77.844)
PB26: U4.E4 U29.3 U30.3 | length 20.3
  L1 - TOP w0.125: v1(44.2,57) 44.3,56.9 45.475,56.9 U30.3@45.525,56.85 ; v1(59.6,53.6) U4.E4@60,53.2
  L3 - SIG w0.125: v1(44.2,57) 48.05,57 48.45,56.6 52.4,56.6 52.9,56.1 57.1,56.1 58,55.2 58,55 59.4,53.6 v1(59.6,53.6)
  L6 - BOT w0.125: U29.3@42.875,56.85 42.925,56.9 44.1,56.9 v1(44.2,57)
PB26_URXD0: J21.14 U29.5 | length 56.9
  L4 - SIG w0.165: v1(48.4,68.375) 49.625,69.6 59.1,69.6 77.915,88.415 J21.14@84.56,88.415
  L6 - BOT w0.165: U29.5@45.525,57.35 45.95,57.35 47.175,58.575 47.175,67.15 v1(48.4,68.375)
PB27: U4.B1 U29.2 U30.2 | length 16.4
  L1 - TOP w0.125: v1(44.2,56.4) 45.475,56.4 U30.2@45.525,56.35 ; v1(57,55.6) U4.B1@57.6,55.6
  L3 - SIG w0.125: v1(44.2,56.4) 47.5,56.4 48.3,55.6 v1(57,55.6)
  L6 - BOT w0.125: U29.2@42.875,56.35 42.925,56.4 v1(44.2,56.4)
PB27_UTXD0: J21.13 U29.6 | length 56.7
  L4 - SIG w0.165: v1(49.25,68.375) 59.975,68.375 77.475,85.875 J21.13@84.56,85.875
  L6 - BOT w0.165: U29.6@45.525,56.85 47.2,56.85 48.125,57.775 48.125,67.25 v1(49.25,68.375) v1@49.3,68.375
PB28: J22.6 U4.C2 U21.49 | length 76
  L1 - TOP w0.125: U21.49@34.5,60.4 35.6,60.4 v1(36.1,60.9) ; U4.C2@58.4,54.8 58.4,55.068 58,55.468 58,55.8 57.8,56 57.484,56 57.2,56.284 v1(57.2,56.7) 57.2,64.7 72,79.5 89.445,79.5 J22.6@90.7,80.755 ; J22.6@90.4,81.055 J22.6@90.7,81.355
  L4 - SIG w0.125: v1(36.1,60.9) 36.6,60.9 38.5,59 42,59 42.4,58.6 51.7,58.6 52.7,57.6 56.7,57.6 57.155,57.145 57.155,56.745 v1(57.2,56.7)
PB29: J22.5 U4.D3 U21.48 | length 77.5
  L1 - TOP w0.125: U21.48@35.4,59.5 35.55,59.5 v1(36.2,60.15) ; U4.D3@59.2,54 58.8,54.4 58.2,54.4 58,54.6 58,55 57.8,55.2 56.834,55.2 56.6,55.434 v1(56.6,56.8) 56.6,64.9 73.7,82 89.405,82 J22.5@90.7,83.295
  L4 - SIG w0.125: v1(36.2,60.15) 36.71,60.15 38.56,58.3 41.6,58.3 42.3,57.6 51.4,57.6 52.2,56.8 v1(56.6,56.8)
PB30: J22.4 U4.D2 U21.53 | length 83.2
  L1 - TOP w0.125: U21.53@32.9,60.4 32.9,61.25 33.6,61.95 v1(34.1,61.95) ; U4.D2@58.4,54 58.132,54 57.732,54.4 56.375,54.4 55.8,54.975 v1(55.8,58.2) 55.8,65.7 74.8,84.7 89.565,84.7 J22.4@90.7,85.835
  L4 - SIG w0.125: v1(34.1,61.95) 36.96,61.95 38.71,60.2 39.381,60.2 40.181,61 45.2,61 46.65,59.55 53.135,59.55 54.485,58.2 v1(55.8,58.2)
PB31: J22.3 U4.C1 | length 56.1
  L1 - TOP w0.125: U4.C1@57.6,54.8 56.75,54.8 56.2,55.35 56.2,65.3 74.9,84 v1(79.5,84) ; J22.3@90.7,89 J22.3@91.013,88.687
  L4 - SIG w0.125: v1(79.5,84) 80.2,84.7 87.025,84.7 J22.3@90.7,88.375
PC0: U4.P17 U21.52 | length 53.2
  L1 - TOP w0.125: U21.52@33.3,60.4 33.3,61.05 33.7,61.45 36.6,61.45 40.35,57.7 40.35,55.55 40.9,55 40.9,51.8 v1(44,48.7) ; U4.P17@70.4,46 71.4,46 v1(71.8,46.4)
  L4 - SIG w0.125: v1(44,48.7) 56.8,48.7 57.3,49.2 61.5,49.2 62.4,50.1 62.4,50.6 62.6,50.8 64.6,50.8 66.4,49 66.4,48.6 66.6,48.4 66.95,48.4 67.2,48.15 67.2,47.73 67.33,47.6 71.3,47.6 71.8,47.1 v1(71.8,46.4)
PC1: U4.N12 U19.29 | length 46.8
  L1 - TOP w0.125: U19.29@32.2,32.35 45.15,32.35 v1(47.5,30) ; U4.N12@66.4,46.8 v1(66.8,46.4)
  L3 - SIG w0.125: v1(47.5,30) 53.3,35.8 53.3,40.1 56.4,43.2 56.4,43.766 57.834,45.2 59.8,45.2 60,45.4 60,46.6 60.2,46.8 66.4,46.8 v1(66.8,46.4)
PC2: R268.1 U4.N14 U18.1 | length 36.2
  L1 - TOP w0.125: v1(67.6,47.2) U4.N14@68,46.8
  L3 - SIG w0.125: v1(51,39.6) 51,41.5 53.6,44.1 53.6,44.4 56.8,47.6 67.2,47.6 v1(67.6,47.2)
  L6 - BOT w0.125: U18.1@38.2,40.45 39.45,40.45 41.7,38.2 48.2,38.2 49.6,39.6 v1(51,39.6)
PC3: J21.15 U4.M15 | length 100.5
  L1 - TOP w0.125: U4.M15@68.8,47.6 v1(69.2,47.2)
  L3 - SIG w0.125: J21.15@84.56,90.955 87.7,87.815 87.7,78.4 89.1,77 93.5,77 104.93,65.57 v1(105,65.57)
  L4 - SIG w0.125: v1(69.2,47.2) 69.6,46.8 69.6,43.025 74.125,38.5 96.075,38.5 100,42.425 100,60.57 100.9,61.47 v1(105,65.57)
PC4: J21.16 U4.M11 | length 54.7
  L1 - TOP w0.125: v1(65.2,48) U4.M11@65.6,47.6
  L3 - SIG w0.125: v1(65.2,48) 65.6,48.4 65.6,50.2 64.8,51 64.8,73.735 J21.16@84.56,93.495
PC5: J21.2 U4.L10 | length 45
  L1 - TOP w0.125: v1(64.4,48) U4.L10@64.8,48.4
  L3 - SIG w0.125: J21.2@61.7,90.955 64,88.655 64,51.8 64.3,51.5 64.3,51.1 64.8,50.6 64.8,48.4 v1(64.4,48)
PC6: U4.K10 U23.2 | length 50.6
  L1 - TOP w0.125: U4.K10@64.8,49.2 v1(65.2,48.8) ; U23.2@102.02,41 102.445,41 102.745,40.7 v1(103,40.7)
  L4 - SIG w0.125: v1(65.2,48.8) 65.2,48.575 65.6,48.175 65.6,47.6 65.575,47.575 66.4,46.75 66.4,42.975 73.875,35.5 97.9,35.5 98.5,36.1 99.6,36.1 103,39.5 v1(103,40.7)
PC6_NCS1: R167.1 U23.4 U24.28 | length 26.6
  L1 - TOP w0.165: U23.4@103.98,40.35 105.3,40.35 R167.1@105.5,40.55 v1(105.5,39.9) ; v1(105,47.825) 107.775,47.825 107.8,47.8 107.8,47.75 U24.28@107.3,47.75
  L6 - BOT w0.165: v1(105,47.825) 105,44.605 106.605,43 107.5,43 107.8,42.7 107.8,42.2 107.5,41.9 104.2,41.9 103.9,41.6 103.9,41.2 104.2,40.9 107.7,40.9 108,40.6 108,38.9 107.75,38.65 106.75,38.65 v1(105.5,39.9)
PC7: J23.14 U4.M16 | length 108.4
  L1 - TOP w0.125: U4.M16@69.6,47.6 v1(70,47.2)
  L4 - SIG w0.125: v1(70,47.2) 70.8,47.2 71.3,46.7 71.3,43.7 75.2,39.8 94.923,39.8 98.5,43.377 98.5,61 110.9,73.4 120.8,73.4 135.785,88.385 J23.14@142.58,88.385
PC8: J23.13 U4.J10 | length 119.7
  L1 - TOP w0.125: U4.J10@64.8,50 v1(65.2,49.6)
  L4 - SIG w0.125: v1(65.2,49.6) 65.6,49.2 65.6,48.6 65.8,48.4 66.175,48.4 66.4,48.175 66.4,47.6 67.2,46.8 67.2,42.8 73.6,36.4 97.9,36.4 98.8,37.3 100,37.3 102.4,39.7 102.4,41.9 103.3,42.8 103.3,45.1 103,45.4 103,61.731 103.769,62.5 108.669,67.4 121.1,67.4 129.169,75.469 139.545,85.845 J23.13@142.58,85.845
PC9: R227.2 U4.D1 | length 60.1
  L1 - TOP w0.125: v1(42.8,33.2) 45.6,33.2 49.2,29.6 57.1,29.6 57.6,29.1 63.8,29.1 64.2,29.5 v1(65.2,29.5) ; v1(56.5,52.8) 56.5,53.5 57,54 U4.D1@57.6,54
  L3 - SIG w0.125: v1(42.8,33.2) 42.8,37.42 41.7,38.52 41.7,45.1 42.8,46.2 42.8,48.2 47.4,52.8 52.5,52.8 52.9,53.2 56.1,53.2 v1(56.5,52.8)
  L6 - BOT w0.125: v1(65.2,29.5) 66.2,28.5 R227.2@66.75,28.5
PC10: U4.E3 U13.1 | length 33.1
  L1 - TOP w0.125: U13.1@44.725,74.05 44.725,73.325 44.4,73 44.4,72 44.6,71.8 45.1,71.8 45.5,71.4 45.5,59.534 46.6,58.434 46.6,56 v1(47.5,55.1) ; v1(58.8,53.6) U4.E3@59.2,53.2
  L3 - SIG w0.125: v1(47.5,55.1) 54.5,55.1 55.3,54.3 58.1,54.3 v1(58.8,53.6)
PC11: C124.2 U4.E2 U13.4 | length 33.3
  L1 - TOP w0.125: U13.4@46.675,74.05 46.675,72.775 ; v1(48.1,54.5) 48.1,55.4 47.1,56.4 47.1,59.1 46.05,60.15 46.05,72.15 46.675,72.775 ; C124.2@48.231,72.269 47.181,72.269 46.675,72.775 ; v1(58,53.6) U4.E2@58.4,53.2
  L3 - SIG w0.125: v1(48.1,54.5) 54.4,54.5 54.9,54 57.6,54 v1(58,53.6)
PC12: J22.14 U4.E1 | length 76.5
  L1 - TOP w0.125: v1(57.2,53.6) U4.E1@57.6,53.2
  L4 - SIG w0.125: v1(57.2,53.6) 58.4,54.8 58.4,56.3 59.2,57.1 59.2,64.5 66.8,72.1 92,72.1 108.275,88.375 J22.14@113.56,88.375
PC13: J22.13 U4.F3 | length 73.9
  L1 - TOP w0.125: U4.F3@59.2,52.4 v1(59.6,52.8)
  L4 - SIG w0.125: v1(59.6,52.8) 59.2,53.2 59.2,55.5 60,56.3 60,62.4 68.3,70.7 93.7,70.7 108.835,85.835 J22.13@113.56,85.835
PC14: R249.1 U4.F5 U32.33 | length 134.6
  L1 - TOP w0.125: U4.F5@60.8,52.4 v1(61.2,52.8) ; v1(138.7,10.2) U32.33@138.7,11.975
  L3 - SIG w0.125: v1(100,64.5) 110.034,64.5 v1(110.566,64.5)
  L4 - SIG w0.125: v1(110.566,64.5) 111.7,63.366 111.7,54.55 112.4,53.85 112.4,45.85 129.7,28.55 129.7,19.2 v1(138.7,10.2)
  L6 - BOT w0.125: v1(61.2,52.8) 61.2,53 60.8,53.4 60.8,56 64.5,59.7 64.5,64 70.5,70 97,70 100,67 v1(100,64.5) ; v1(138.7,10.2) 138.8,10.1 R249.1@139.75,10.1
PC15: R271.2 U4.F2 U23.1 U35.6 U36.6 U37.3 | length 135.6
  L1 - TOP w0.125: v1(58,52.8) U4.F2@58.4,52.4 ; U23.1@102.02,41.65 102.85,41.65 v1(103,41.5) ; v1(122.9,14) 122.9,14.9 U37.3@122.95,14.95
  L3 - SIG w0.125: v1(103,41.5) 102.2,40.7 102.2,38.7 101.6,38.1 101.6,36.9 122.9,15.6 v1(122.9,14)
  L6 - BOT w0.125: v1(58,52.8) 58.4,53.2 58.4,54 59.2,54.8 59.2,55.7 63.5,60 63.5,65.45 69.05,71 97.6,71 104.1,64.5 104.1,44.7 103,43.6 v1(103,41.5) 102.2,41.5 101.3,42.4 97.121,42.4 96.371,41.65 ; U35.6@95.796,41.65 96.371,41.65 ; U36.6@95.8,38.95 96.05,38.95 96.7,39.6 96.7,41.321 96.371,41.65 ; v1(122.9,14) 123.55,14 R271.2@123.75,14.2
PC16: R153.2 U4.G6 U21.45 | length 41.1
  L1 - TOP w0.125: U21.45@35.413,58.313 U21.45@35.4,58.3 38,58.3 38.5,57.8 38.5,56.7 v1(39,56.2) 38.5,55.7 37.7,55.7 37.5,55.5 37.5,54.8 37.74,54.56 38.64,54.56 39.35,53.85 39.35,52.3 39.15,52.1 38.7,52.1 38.5,52.3 v1(38.5,53.8) ; v1(61.2,52) U4.G6@61.6,51.6
  L4 - SIG w0.125: v1(38.5,53.8) 48,53.8 49.3,55.1 53,55.1 53.9,54.2 53.9,52.7 54.2,52.4 58.975,52.4 59.2,52.175 59.2,51.825 59.425,51.6 60.8,51.6 v1(61.2,52)
  L6 - BOT w0.125: v1(39,56.2) R153.2@39.65,56.2
PC17: U4.F1 U12.1 | length 40.4
  L1 - TOP w0.125: v1(42.5,29.5) 42.5,28.382 44.582,26.3 U12.1@46.045,26.3 ; v1(57.2,52.8) U4.F1@57.6,52.4
  L3 - SIG w0.125: v1(42.5,29.5) 42.5,32 44.1,33.6 44.1,48.066 48.434,52.4 56.8,52.4 v1(57.2,52.8)
PC18: J21.4 U4.H6 | length 45.8
  L1 - TOP w0.125: v1(54.4,52.8) 54.4,66.7 60.5,72.8 60.5,81.3 61.3,82.1 62.3,82.1 63,82.8 63,84.575 J21.4@61.7,85.875 ; v1(61.2,51.2) U4.H6@61.6,50.8
  L6 - BOT w0.125: v1(54.4,52.8) 55.6,51.6 60.8,51.6 v1(61.2,51.2)
PC19: J21.5 U4.G2 | length 38.7
  L1 - TOP w0.125: U4.G2@58.4,51.6 58,52 54.634,52 54,52.634 54,67.1 60,73.1 60,81.635 J21.5@61.7,83.335
PC20: J21.6 U4.G3 | length 36.5
  L1 - TOP w0.125: v1(55,52.8) 55,66.5 63,74.5 63,79.495 J21.6@61.7,80.795 ; v1(58.8,52) U4.G3@59.2,51.6
  L6 - BOT w0.125: v1(55,52.8) 55.8,52 v1(58.8,52)
PC21: J21.3 U4.G1 | length 43.7
  L1 - TOP w0.125: U4.G1@57.6,51.6 54.469,51.6 53.6,52.469 53.6,67.5 59,72.9 59,85.715 J21.3@61.7,88.415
